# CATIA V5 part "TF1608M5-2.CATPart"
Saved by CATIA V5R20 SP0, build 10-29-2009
Part number: TF1608M5-2
Revision: ANY
Definition: UNKNOWN
Nomenclature: TF1608M5-2
Source: Unknown
Bounding box of the stored display mesh (mm): x -3.662 to 3.662, y 0 to 3.95, z -3.85 to 3.85
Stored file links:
  C:\Users\Utente\Desktop\IO LAVORO\3D X SITO CF\CUMSA\3D files RCM\RCM 163808\TF1608M5-2.CATPart
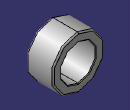
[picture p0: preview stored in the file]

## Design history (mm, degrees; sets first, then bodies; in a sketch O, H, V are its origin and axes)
Body1 "Chaflán2" (main body)
  Solid1: solid without history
